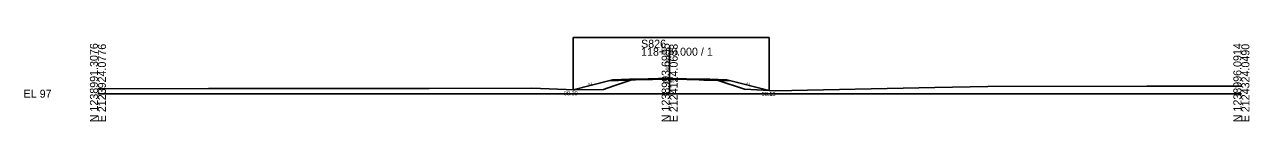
# Model space of a CAD drawing. Extents: x 2119282 to 2119710, y 1215030 to 1220057.
# Drawn here: x 2119281.9 to 2119710.4, y 1216530.1 to 1216559.4 of the extents above; entities that cross this region are included whole.
import ezdxf

# ---------------------------------------------------------------- set-up
doc = ezdxf.new("R2010")
doc.units = 0
for name, color, linetype in [('XS_CELL', 7, 'Continuous'), ('XS_M_DITCH', 7, 'Continuous'), ('XS_M_SHAPES_EARTHWORK', 7, 'Continuous'), ('XS_P_FINISHED_GRADE', 7, 'Continuous'), ('XS_P_FINISHED_GRADE_ELEV_TX', 7, 'Continuous'), ('XS_P_SUBGRADE_GRANULAR', 7, 'Continuous'), ('XS_P_SUBGRADE_PAVEMENT', 7, 'Continuous'), ('XS_P_TX_DCH', 7, 'Continuous'), ('XS_P_TX_FS_BS', 7, 'Continuous'), ('XS_X_GROUND', 7, 'Continuous'), ('XS_X_GROUND_TX', 7, 'Continuous')]:
    doc.layers.add(name, color=color, linetype=linetype)

msp = doc.modelspace()

# ---------------------------------------------------------------- linework, layer by layer
at = {"layer": 'XS_CELL'}
for p, q in [((2119507.6, 1216539.8), (2119507.6, 1216555.91)), ((2119307.6, 1216539.8), (2119507.6, 1216539.8)), ((2119507.6, 1216539.8), (2119707.6, 1216539.8))]:
    msp.add_line(p, q, dxfattribs=at)
at = {"layer": 'XS_M_DITCH'}
for p, q in [((2119473.79, 1216541.19), (2119473.79, 1216559.44)), ((2119473.79, 1216559.44), (2119542.42, 1216559.44)), ((2119542.42, 1216540.94), (2119542.42, 1216559.44))]:
    msp.add_line(p, q, dxfattribs=at)
at = {"layer": 'XS_M_SHAPES_EARTHWORK'}
for p, q in [((2119486.25, 1216544.3), (2119473.79, 1216541.19)), ((2119493.17, 1216544.58), (2119486.25, 1216544.3)), ((2119488.13, 1216542.61), (2119494, 1216544.6)), ((2119494, 1216544.6), (2119493.17, 1216544.58)), ((2119494.34, 1216544.71), (2119494, 1216544.6)), ((2119494, 1216544.6), (2119495.6, 1216544.63)), ((2119495.6, 1216544.85), (2119494.34, 1216544.71)), ((2119522.04, 1216544.58), (2119519.6, 1216544.63)), ((2119519.6, 1216544.63), (2119519.6, 1216544.63)), ((2119519.6, 1216544.63), (2119519.6, 1216544.58)), ((2119519.6, 1216544.58), (2119520.19, 1216544.55)), ((2119520.19, 1216544.55), (2119521.57, 1216544.51)), ((2119521.57, 1216544.51), (2119524.56, 1216544.39)), ((2119528.95, 1216544.3), (2119522.04, 1216544.58)), ((2119524.56, 1216544.39), (2119533.78, 1216541.37)), ((2119542.42, 1216540.94), (2119528.95, 1216544.3)), ((2119473.79, 1216541.19), (2119474.48, 1216541.17)), ((2119474.48, 1216541.17), (2119484.45, 1216541.33)), ((2119484.45, 1216541.33), (2119488.13, 1216542.61)), ((2119533.78, 1216541.37), (2119542.42, 1216540.94))]:
    msp.add_line(p, q, dxfattribs=at)
msp.add_lwpolyline([(2119495.6, 1216544.63), (2119495.6, 1216544.63), (2119495.6, 1216544.85)], dxfattribs=at)
at = {"layer": 'XS_P_FINISHED_GRADE'}
for p, q in [((2119487.6, 1216544.64), (2119473.79, 1216541.19)), ((2119493.6, 1216544.88), (2119487.6, 1216544.64)), ((2119495.6, 1216544.92), (2119493.6, 1216544.88)), ((2119507.6, 1216545.16), (2119495.6, 1216544.92)), ((2119507.6, 1216545.16), (2119519.6, 1216544.92)), ((2119519.6, 1216544.92), (2119521.6, 1216544.88)), ((2119521.6, 1216544.88), (2119527.6, 1216544.64)), ((2119527.6, 1216544.64), (2119542.42, 1216540.94))]:
    msp.add_line(p, q, dxfattribs=at)
at = {"layer": 'XS_P_SUBGRADE_GRANULAR'}
for p, q in [((2119493.17, 1216544.58), (2119486.25, 1216544.3)), ((2119522.04, 1216544.58), (2119528.95, 1216544.3))]:
    msp.add_line(p, q, dxfattribs=at)
at = {"layer": 'XS_P_SUBGRADE_PAVEMENT'}
for p, q in [((2119493.6, 1216544.88), (2119493.17, 1216544.58)), ((2119495.61, 1216544.63), (2119493.17, 1216544.58)), ((2119507.6, 1216544.87), (2119495.61, 1216544.63)), ((2119507.6, 1216544.87), (2119519.6, 1216544.63)), ((2119519.6, 1216544.63), (2119522.04, 1216544.58)), ((2119521.6, 1216544.88), (2119522.04, 1216544.58))]:
    msp.add_line(p, q, dxfattribs=at)
at = {"layer": 'XS_X_GROUND'}
for p, q in [((2119488.13, 1216542.61), (2119494.34, 1216544.71)), ((2119494.34, 1216544.71), (2119496.11, 1216544.9)), ((2119496.11, 1216544.9), (2119496.46, 1216544.94)), ((2119496.46, 1216544.94), (2119503.68, 1216545.08)), ((2119503.68, 1216545.08), (2119507.6, 1216545.16)), ((2119507.6, 1216545.16), (2119508.17, 1216545.17)), ((2119508.17, 1216545.17), (2119513.37, 1216544.9)), ((2119513.37, 1216544.9), (2119520.19, 1216544.55)), ((2119520.19, 1216544.55), (2119521.57, 1216544.51)), ((2119521.57, 1216544.51), (2119524.56, 1216544.39)), ((2119524.56, 1216544.39), (2119533.78, 1216541.37)), ((2119307.6, 1216541.51), (2119346.23, 1216541.57)), ((2119346.23, 1216541.57), (2119365.52, 1216541.59)), ((2119365.52, 1216541.59), (2119423.46, 1216541.68)), ((2119423.46, 1216541.68), (2119459.33, 1216541.74)), ((2119459.33, 1216541.74), (2119474.48, 1216541.17)), ((2119474.48, 1216541.17), (2119484.45, 1216541.33)), ((2119484.45, 1216541.33), (2119488.13, 1216542.61)), ((2119533.78, 1216541.37), (2119544.76, 1216540.82)), ((2119544.76, 1216540.82), (2119600.36, 1216541.94)), ((2119600.36, 1216541.94), (2119618.9, 1216542.31)), ((2119618.9, 1216542.31), (2119674.53, 1216542.44)), ((2119674.53, 1216542.44), (2119685.26, 1216542.46)), ((2119685.26, 1216542.46), (2119688.86, 1216542.48)), ((2119688.86, 1216542.48), (2119697.5, 1216542.44)), ((2119697.5, 1216542.44), (2119707.6, 1216542.41))]:
    msp.add_line(p, q, dxfattribs=at)

# ---------------------------------------------------------------- texts
at = {"layer": 'XS_CELL'}
for s, p in [('N 1238991.3076', (2119307.6, 1216529.8)), ('E 2123924.0776', (2119310.4, 1216529.8)), ('N 1238993.6995', (2119507.6, 1216529.8)), ('E 2124124.0633', (2119510.4, 1216529.8)), ('N 1238996.0914', (2119707.6, 1216529.8)), ('E 2124324.0490', (2119710.4, 1216529.8))]:
    msp.add_text(s, height=2.8, rotation=90, dxfattribs=at).set_placement(p)
for s, p in [('S826', (2119497.6, 1216555.91)), ('118+00.000 / 1', (2119497.6, 1216553.11)), ('EL 97', (2119281.6, 1216538.4))]:
    msp.add_text(s, height=2.8, dxfattribs=at).set_placement(p)
at = {"layer": 'XS_P_FINISHED_GRADE_ELEV_TX'}
msp.add_text('102.36', height=1.25, rotation=90, dxfattribs=at).set_placement((2119507.45, 1216547.04))
at = {"layer": 'XS_P_TX_DCH'}
for s, p in [('98.39', (2119470.61, 1216539.24)), ('98.13', (2119539.8, 1216539.02))]:
    msp.add_text(s, height=1.4, dxfattribs=at).set_placement(p)
at = {"layer": 'XS_P_TX_FS_BS'}
for rotation, p in [(14.015, (2119479.11, 1216542.76)), (345.9638, (2119534.27, 1216543.13))]:
    msp.add_text('4:1', height=0.8, rotation=rotation, dxfattribs=at).set_placement(p)
at = {"layer": 'XS_X_GROUND_TX'}
msp.add_text('102.36', height=1, dxfattribs=at).set_placement((2119505.03, 1216543.75))

doc.saveas('drawing.dxf')
